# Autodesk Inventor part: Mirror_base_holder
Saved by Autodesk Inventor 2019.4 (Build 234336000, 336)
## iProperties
Created: 2019-10
Part Number: Mirror_base_holder
Material: Generic
Document SubType Name: Modeling
Designer: Administrator
Density: 1 g/cm^3
Appearance: Default
Title: Mirror_base_holder
Author: Administrator
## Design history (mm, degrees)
feature "Body1"
body "Solid1"
